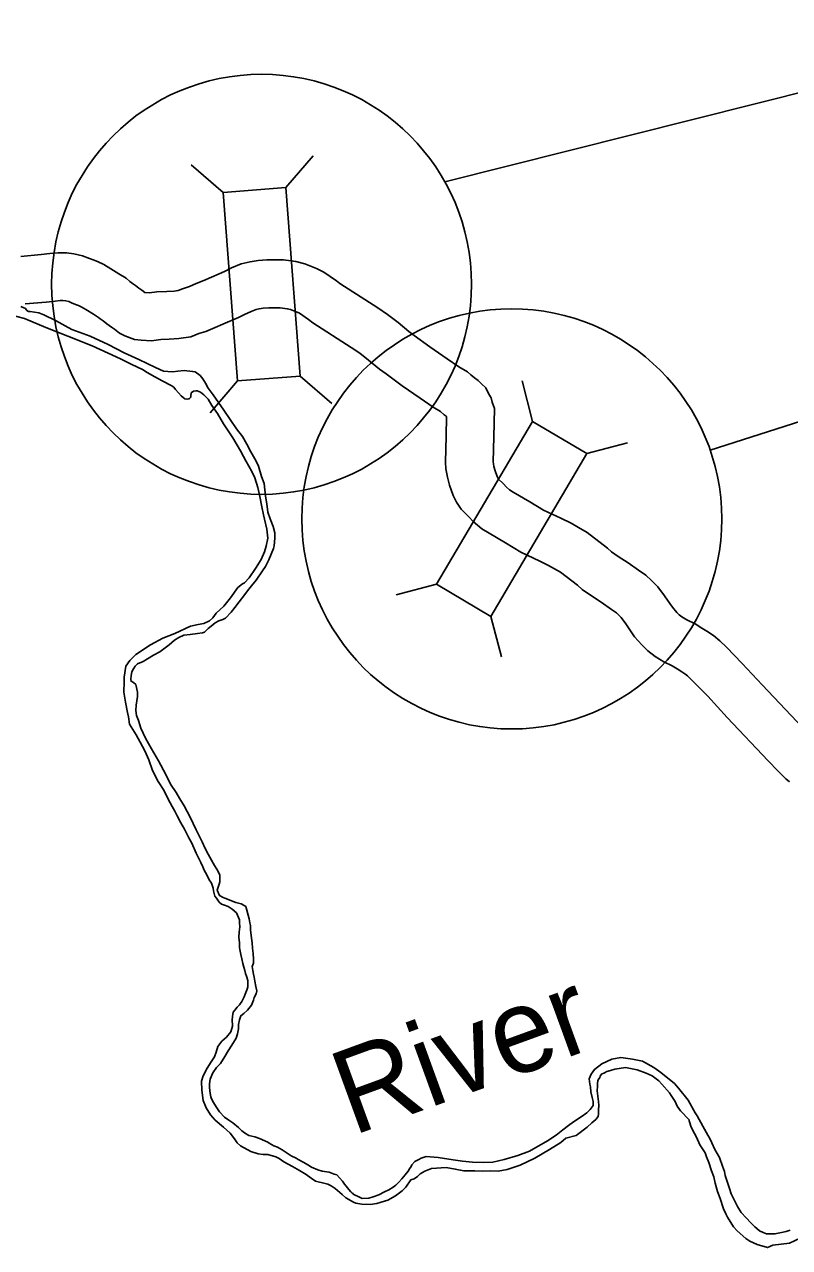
# Model space of a CAD drawing. Extents: x 79818 to 83933, y 50884 to 53307.
# Drawn here: x 81014.4 to 81078.5, y 53005.3 to 53107.7 of the extents above; entities that cross this region are included whole.
import ezdxf

# ---------------------------------------------------------------- set-up
doc = ezdxf.new("R2010")
doc.units = 0
for name, color, linetype in [('Default', 7, 'Continuous'), ('Level 10', 7, 'Continuous'), ('Level 20', 7, 'Continuous'), ('Level 9', 7, 'Continuous')]:
    doc.layers.add(name, color=color, linetype=linetype)

msp = doc.modelspace()

# ---------------------------------------------------------------- linework, layer by layer
at = {"layer": 'Default'}
for p in [(81049.64, 53094.55), (81071.88, 53072.06)]:
    msp.add_line(p, (81483.45, 53203.33), dxfattribs=at)
for centre in [(81034.28, 53085.95), (81055.25, 53066.3)]:
    msp.add_circle(centre, 17.6, dxfattribs=at)
at = {"layer": 'Level 10'}
for points in [[(81014.11, 53088.29), (81015.81, 53088.44), (81016.53, 53088.53), (81017.24, 53088.6), (81017.92, 53088.58), (81018.53, 53088.51), (81019.28, 53088.35), (81019.86, 53088.12), (81020.17, 53087.99), (81020.52, 53087.86), (81021.05, 53087.6), (81021.64, 53087.26), (81022.3, 53086.83), (81022.92, 53086.46), (81023.24, 53086.2), (81023.46, 53086.03), (81023.7, 53085.84), (81023.99, 53085.63), (81024.25, 53085.45), (81024.5, 53085.27), (81024.52, 53085.26), (81024.53, 53085.26), (81024.89, 53085.24), (81025.49, 53085.32), (81026.33, 53085.34), (81026.94, 53085.39), (81027.3, 53085.43), (81027.65, 53085.58), (81028.23, 53085.76), (81028.8, 53086.01), (81029.45, 53086.28), (81030.73, 53086.84), (81031.16, 53087.03), (81031.76, 53087.32), (81032.56, 53087.66), (81033.31, 53087.84), (81033.98, 53087.94), (81034.73, 53087.99), (81035.17, 53087.99), (81036.11, 53087.99), (81037.14, 53087.85), (81037.9, 53087.68), (81038.88, 53087.29), (81039.5, 53086.98), (81040.55, 53086.24), (81040.85, 53086.02), (81044.01, 53083.98), (81044.84, 53083.41), (81045.72, 53082.74), (81046.62, 53082), (81047.07, 53081.67), (81048.38, 53080.71), (81049.83, 53079.7), (81050.81, 53079.04), (81051.53, 53078.61), (81051.83, 53078.38), (81052.13, 53078.11), (81052.43, 53077.88), (81052.7, 53077.6), (81053.07, 53077.27), (81053.34, 53076.74), (81053.51, 53076.43), (81053.61, 53076.07), (81053.8, 53075.55), (81053.74, 53073.15)], [(81014.45, 53084.31), (81016.22, 53084.46), (81016.98, 53084.55), (81017.39, 53084.59), (81017.62, 53084.59), (81017.87, 53084.56), (81018.12, 53084.5), (81018.35, 53084.41), (81018.69, 53084.27), (81018.93, 53084.18), (81019.17, 53084.06), (81019.55, 53083.84), (81020.18, 53083.44), (81020.62, 53083.17), (81020.75, 53083.07), (81020.99, 53082.88), (81021.3, 53082.64), (81021.69, 53082.35), (81021.95, 53082.18), (81022.38, 53081.87), (81022.82, 53081.63), (81023.62, 53081.32), (81024.19, 53081.27), (81025.06, 53081.23), (81025.82, 53081.33), (81026.53, 53081.35), (81027.33, 53081.41), (81028.35, 53081.54), (81029.02, 53081.82), (81029.61, 53082), (81030.38, 53082.33), (81031.02, 53082.61), (81032.35, 53083.18), (81032.86, 53083.41), (81033.4, 53083.67), (81033.83, 53083.85), (81034.07, 53083.91), (81034.4, 53083.96), (81034.88, 53083.99), (81035.16, 53083.99), (81035.85, 53083.99), (81036.43, 53083.91), (81036.7, 53083.85), (81037.25, 53083.63), (81037.45, 53083.53), (81038.2, 53083), (81038.57, 53082.73), (81041.79, 53080.65), (81042.5, 53080.17), (81043.23, 53079.61), (81044.17, 53078.83), (81044.71, 53078.44), (81046.05, 53077.45), (81047.58, 53076.4), (81048.65, 53075.67), (81049.27, 53075.3), (81049.27, 53075.3), (81049.57, 53075.03), (81049.74, 53074.9), (81049.78, 53074.86), (81049.74, 53073.25)], [(81049.74, 53073.23), (81049.7, 53071.04), (81049.72, 53070.49), (81049.85, 53069.79), (81050.04, 53069.11), (81050.34, 53068.27), (81050.63, 53067.71), (81051, 53067.12), (81051.64, 53066.48), (81052.02, 53066.07), (81052.73, 53065.46), (81053.36, 53065.09), (81054.72, 53064.29), (81056.02, 53063.5), (81057.61, 53062.77), (81058.34, 53062.4), (81058.84, 53062.12), (81059.32, 53061.84), (81060.75, 53060.74), (81061.15, 53060.39), (81061.92, 53059.85), (81062.75, 53059.31), (81063.6, 53058.72), (81064.02, 53058.43), (81064.17, 53058.29), (81064.42, 53058.03), (81064.81, 53057.5), (81065.21, 53056.93), (81065.55, 53056.43), (81066.15, 53055.74), (81066.65, 53055.24), (81067.26, 53054.78), (81068, 53054.33), (81068.68, 53053.99), (81069.1, 53053.74), (81069.5, 53053.49), (81069.76, 53053.33), (81069.97, 53053.14), (81070.46, 53052.68), (81071.67, 53051.44), (81073.31, 53049.67), (81076.74, 53046.02), (81077.55, 53045.19), (81078.21, 53044.53), (81078.54, 53044.27)], [(81053.74, 53073.17), (81053.7, 53071.08), (81053.71, 53070.91), (81053.75, 53070.7), (81053.85, 53070.33), (81054.03, 53069.85), (81054.11, 53069.68), (81054.14, 53069.64), (81054.52, 53069.26), (81054.81, 53068.95), (81055.06, 53068.73), (81055.38, 53068.54), (81056.77, 53067.72), (81057.9, 53067.04), (81059.35, 53066.37), (81060.22, 53065.93), (81060.84, 53065.58), (81061.56, 53065.16), (81063.28, 53063.84), (81063.62, 53063.55), (81064.16, 53063.16), (81065, 53062.62), (81065.87, 53062), (81066.49, 53061.58), (81066.97, 53061.15), (81067.48, 53060.61), (81068.05, 53059.85), (81068.5, 53059.2), (81068.72, 53058.89), (81069.09, 53058.46), (81069.29, 53058.26), (81069.5, 53058.1), (81069.93, 53057.84), (81070.61, 53057.5), (81071.19, 53057.15), (81071.61, 53056.89), (81072.17, 53056.54), (81072.68, 53056.08), (81073.26, 53055.54), (81074.57, 53054.19), (81076.23, 53052.4), (81079.64, 53048.78)]]:
    msp.add_lwpolyline(points, dxfattribs=at)
at = {"layer": 'Level 20'}
for p, q in [((81036.32, 53094.05), (81038.61, 53096.72)), ((81031.05, 53093.65), (81028.38, 53095.95)), ((81037.51, 53078.26), (81040.18, 53075.96)), ((81032.25, 53077.86), (81029.96, 53075.19)), ((81057, 53074.46), (81056.12, 53077.87)), ((81061.55, 53071.78), (81064.96, 53072.66)), ((81048.95, 53060.82), (81045.55, 53059.94)), ((81053.5, 53058.13), (81054.38, 53054.73))]:
    msp.add_line(p, q, dxfattribs=at)
for points in [[(81037.51, 53078.26), (81036.32, 53094.05), (81031.05, 53093.65), (81032.25, 53077.86)], [(81053.5, 53058.13), (81061.55, 53071.78), (81057, 53074.46), (81048.95, 53060.82)]]:
    msp.add_lwpolyline(points, close=True, dxfattribs=at)
at = {"layer": 'Level 9'}
for points in [[(81012.48, 53083.59), (81014.42, 53083.09), (81016.2, 53082.32), (81018.04, 53081.6), (81020.09, 53080.79), (81021.43, 53080.18), (81022.45, 53079.7), (81023.4, 53079.23), (81024.3, 53078.81), (81024.69, 53078.56), (81025.33, 53078.2), (81026, 53077.83), (81026.69, 53077.47), (81026.91, 53077.34), (81027.06, 53077.15), (81027.32, 53076.87), (81027.54, 53076.6), (81027.7, 53076.46), (81027.85, 53076.36), (81028.03, 53076.32), (81028.18, 53076.35), (81028.25, 53076.39), (81028.35, 53076.5), (81028.35, 53076.62), (81028.39, 53076.85), (81028.58, 53076.99), (81028.76, 53077.02), (81028.89, 53077.03), (81029.16, 53076.91), (81029.44, 53076.68), (81029.79, 53076.34), (81030.11, 53075.8), (81030.57, 53075.12), (81031.1, 53074.27), (81031.87, 53073.1), (81032.5, 53072), (81032.77, 53071.52), (81032.95, 53071.16), (81033.47, 53070.28), (81033.71, 53069.74), (81033.96, 53068.93), (81034.12, 53068.17), (81034.29, 53067.32), (81034.43, 53066.64), (81034.52, 53066.27), (81034.73, 53065.45), (81034.79, 53064.67), (81034.66, 53064), (81034.51, 53063.53), (81034.25, 53062.89), (81033.77, 53062.13), (81033.23, 53061.35), (81032.86, 53060.95), (81032.68, 53060.87), (81032.28, 53060.55), (81031.67, 53059.69), (81031.11, 53058.99), (81030.47, 53058.4), (81030.19, 53058.02), (81029.92, 53057.76), (81029.45, 53057.53), (81028.95, 53057.45), (81028.31, 53057.32), (81027.02, 53056.7), (81026, 53056.3), (81024.96, 53055.76), (81023.74, 53054.94), (81023.23, 53054.44), (81022.91, 53053.96), (81022.77, 53053.04), (81022.77, 53052.68), (81022.74, 53051.79), (81022.86, 53050.95), (81023.04, 53050.08), (81023.11, 53049.72), (81023.21, 53049.09), (81023.77, 53048.2), (81024.11, 53047.58), (81024.49, 53046.88), (81024.82, 53046.12)], [(81014.1, 53084.1), (81014.48, 53083.93), (81014.61, 53083.77), (81014.75, 53083.67), (81014.89, 53083.67), (81015.6, 53083.56), (81016.03, 53083.4), (81017, 53082.91), (81018.38, 53082.17), (81019.9, 53081.61), (81021.41, 53080.9), (81022.76, 53080.21), (81023.98, 53079.64), (81025.39, 53078.97), (81026.05, 53078.67), (81026.43, 53078.64), (81026.85, 53078.63), (81027.27, 53078.67), (81027.78, 53078.72), (81028.5, 53078.66), (81028.7, 53078.62), (81029.13, 53078.32), (81029.36, 53078.02), (81029.59, 53077.67), (81029.81, 53077.25), (81030.23, 53076.68), (81031.11, 53075.42), (81032.18, 53073.83), (81032.68, 53073.19), (81033.05, 53072.56), (81033.37, 53071.91), (81033.82, 53071.13), (81034.01, 53070.72), (81034.28, 53069.84), (81034.49, 53069.27), (81034.62, 53068.2), (81034.73, 53067.56), (81034.81, 53066.86), (81035, 53066.29), (81035.24, 53065.66), (81035.4, 53065.13), (81035.38, 53064.67), (81035.33, 53064.05), (81035.28, 53063.82), (81034.9, 53062.88), (81034.6, 53062.32), (81034.36, 53061.95), (81033.83, 53061.17), (81033.44, 53060.7), (81033.11, 53060.27), (81032.87, 53059.97), (81032.39, 53059.35), (81032.05, 53058.87), (81031.72, 53058.49), (81031.25, 53057.97), (81031.02, 53057.88), (81030.69, 53057.76), (81030.39, 53057.58), (81030.04, 53057.31), (81029.8, 53057.11), (81029.5, 53056.81), (81029.32, 53056.76), (81028.92, 53056.7), (81028.28, 53056.6), (81027.76, 53056.55), (81027.34, 53056.36), (81026.99, 53056.15), (81026.54, 53055.76), (81025.74, 53055.15), (81025.23, 53054.87), (81024.73, 53054.57), (81024.35, 53054.36), (81023.88, 53054.16), (81023.69, 53053.95), (81023.53, 53053.73), (81023.39, 53053.48), (81023.34, 53053.19), (81023.31, 53052.84), (81023.34, 53052.7), (81023.54, 53052.58), (81023.75, 53052.41), (81023.87, 53051.77), (81023.87, 53051.42), (81023.77, 53050.7), (81023.75, 53050.24), (81023.79, 53049.84), (81023.96, 53049.41), (81024.16, 53048.77), (81024.55, 53047.94), (81025.04, 53047.02), (81025.64, 53046.04)], [(81024.82, 53046.12), (81025.13, 53045.22), (81025.61, 53044.31), (81026.08, 53043.56), (81026.44, 53042.81), (81026.78, 53042.2), (81027, 53041.81), (81027.21, 53041.41), (81027.52, 53040.83), (81027.82, 53040.29), (81028.18, 53039.59), (81028.43, 53039.13), (81028.8, 53038.29), (81029.2, 53037.51), (81029.36, 53037.15), (81029.46, 53036.87), (81029.58, 53036.66), (81029.93, 53035.98), (81030.06, 53035.84), (81030.12, 53035.69), (81030.21, 53035.37), (81030.24, 53035.13), (81030.35, 53034.69), (81030.49, 53034.52), (81030.72, 53034.19), (81030.93, 53034.03), (81031.17, 53033.95), (81031.47, 53033.82), (81031.8, 53033.61)], [(81025.64, 53046.04), (81026.25, 53044.87), (81026.65, 53044.07), (81027.11, 53043.37), (81027.44, 53042.84), (81027.78, 53042.27), (81028.3, 53041.31), (81028.8, 53040.25), (81029.29, 53039.23), (81029.55, 53038.69), (81029.79, 53038.22), (81030.22, 53037.45), (81030.33, 53037.25), (81030.6, 53036.82), (81030.77, 53036.46), (81030.79, 53035.9), (81030.71, 53035.7), (81030.56, 53035.2), (81030.75, 53034.74), (81031.07, 53034.59), (81031.19, 53034.53), (81032.12, 53034.15), (81032.56, 53034.05), (81032.83, 53033.92), (81032.96, 53033.83)], [(81031.8, 53033.61), (81032.19, 53033.29), (81032.43, 53032.71), (81032.44, 53032.47), (81032.45, 53032.13), (81032.4, 53031.67), (81032.36, 53031.26), (81032.42, 53030.79), (81032.43, 53030.39), (81032.46, 53030.23), (81032.55, 53029.79), (81032.61, 53029.45), (81032.72, 53029.04), (81032.8, 53028.75), (81032.88, 53028.47), (81032.94, 53028.2), (81033.01, 53027.99), (81033.12, 53027.62), (81033.13, 53027.52), (81033.13, 53027.1), (81033.08, 53026.89), (81032.91, 53026.48), (81032.82, 53026.25), (81032.62, 53025.86), (81032.44, 53025.59), (81032.23, 53025.39), (81032.03, 53025.15), (81031.91, 53024.96), (81031.83, 53024.62), (81031.81, 53024.3), (81031.83, 53023.89), (81031.83, 53023.81), (81031.69, 53023.32), (81031.34, 53022.89), (81030.96, 53022.53), (81030.62, 53022.09), (81030.48, 53021.63), (81030.32, 53021.23), (81030.05, 53020.81), (81029.71, 53020.28), (81029.39, 53019.64), (81029.24, 53019.19), (81029.27, 53018.44), (81029.39, 53017.58), (81029.64, 53016.97), (81030.01, 53016.38), (81030.4, 53015.92), (81031.09, 53015.34), (81031.64, 53014.84), (81032, 53014.37), (81032.23, 53014.02), (81032.52, 53013.77), (81033.38, 53013.3), (81033.99, 53013.09), (81034.41, 53013.04), (81034.79, 53013.05), (81035.47, 53012.84), (81035.74, 53012.72), (81036.15, 53012.44), (81036.86, 53012.03), (81037.45, 53011.71), (81038.01, 53011.38), (81038.44, 53011.07), (81038.8, 53010.82), (81039.6, 53010.62), (81039.83, 53010.55), (81040.11, 53010.43), (81040.44, 53010.21), (81040.83, 53009.86), (81041.02, 53009.7), (81041.35, 53009.41), (81041.98, 53009.04), (81042.18, 53008.96), (81042.69, 53008.89), (81043.37, 53008.87), (81043.93, 53008.93), (81044.29, 53009.05), (81044.85, 53009.23), (81045.5, 53009.58), (81046.06, 53010.01), (81046.36, 53010.31), (81046.8, 53010.93), (81047.06, 53011), (81047.35, 53011.2), (81047.57, 53011.43), (81047.97, 53011.65), (81048.52, 53011.88), (81049.76, 53011.95), (81050.51, 53011.83), (81051.23, 53011.69), (81052.14, 53011.69), (81052.76, 53011.66), (81053.46, 53011.67), (81054.1, 53011.64), (81054.87, 53011.79), (81055.96, 53012.15), (81057.17, 53012.73), (81058.4, 53013.48), (81059.35, 53014.06), (81059.77, 53014.41), (81060.65, 53014.63)], [(81032.96, 53033.83), (81033.23, 53032.78), (81033.29, 53032.46), (81033.35, 53032.22), (81033.36, 53031.86), (81033.39, 53031.61), (81033.46, 53030.97), (81033.49, 53030.78), (81033.51, 53030.32), (81033.58, 53029.9), (81033.59, 53029.42), (81033.61, 53029.07), (81033.5, 53028.79), (81033.54, 53028.47), (81033.6, 53028.16), (81033.65, 53027.91), (81033.71, 53027.56), (81033.81, 53027.12), (81033.88, 53026.77), (81033.82, 53026.5), (81033.66, 53026.21), (81033.59, 53025.97), (81033.44, 53025.55), (81033.1, 53025.13), (81032.78, 53024.87), (81032.54, 53024.67), (81032.42, 53024.34), (81032.34, 53023.94), (81032.34, 53023.58), (81032.26, 53023.15), (81032.16, 53022.8), (81031.78, 53022.21), (81031.48, 53021.73), (81031.19, 53021.26), (81030.83, 53020.66), (81030.51, 53020.33), (81030.2, 53019.88), (81029.98, 53019.36), (81029.92, 53018.97), (81029.91, 53018.73), (81029.94, 53018.36), (81030.02, 53017.89), (81030.09, 53017.71), (81030.25, 53017.39), (81030.46, 53017.03), (81030.74, 53016.61), (81031.17, 53016.17), (81031.52, 53015.91), (81031.88, 53015.69), (81032.33, 53015.32), (81032.63, 53015.04), (81032.85, 53014.85), (81033.2, 53014.64), (81033.71, 53014.52), (81034.11, 53014.39), (81034.8, 53014.07), (81034.91, 53014), (81035.3, 53013.78), (81035.62, 53013.67), (81035.99, 53013.43), (81036.43, 53013.15), (81036.77, 53012.94), (81037.18, 53012.74), (81037.35, 53012.63), (81037.82, 53012.37), (81038.16, 53012.18), (81038.45, 53011.99), (81039, 53011.75), (81039.37, 53011.65), (81039.94, 53011.58), (81040.35, 53011.41), (81040.59, 53011.33), (81041.05, 53010.81), (81041.24, 53010.57), (81041.37, 53010.4), (81041.58, 53010.12), (81041.75, 53009.92), (81041.87, 53009.81), (81041.95, 53009.77), (81041.96, 53009.72), (81042.54, 53009.44), (81042.72, 53009.37), (81043.27, 53009.39), (81043.62, 53009.49), (81044.11, 53009.67), (81044.59, 53009.92), (81044.95, 53010.1), (81045.3, 53010.31), (81045.52, 53010.47), (81045.79, 53010.73), (81046.03, 53011.02), (81046.31, 53011.34), (81046.56, 53011.65), (81046.69, 53011.84), (81046.81, 53012.03), (81046.87, 53012.19), (81047.11, 53012.47), (81047.45, 53012.64), (81047.66, 53012.74), (81048.08, 53012.87), (81049.09, 53012.79)], [(81049.09, 53012.79), (81050.35, 53012.61), (81051.11, 53012.5), (81051.95, 53012.41), (81052.92, 53012.37), (81053.67, 53012.41), (81054.6, 53012.64), (81055.77, 53012.97), (81056.73, 53013.33), (81058.23, 53014.2), (81058.98, 53014.67), (81059.53, 53015.11), (81060, 53015.47), (81060.42, 53015.77), (81061.07, 53016.19), (81061.54, 53016.53), (81061.83, 53016.81), (81062.07, 53017.15), (81062.06, 53017.48), (81061.99, 53017.83), (81061.88, 53018.3), (81061.84, 53018.71), (81061.8, 53018.94), (81061.75, 53019.38), (81061.91, 53019.77), (81062.17, 53020.18), (81062.79, 53020.64), (81063.65, 53021.03), (81064.38, 53021.16), (81065.37, 53021.03), (81066.21, 53020.86), (81067.16, 53020.34), (81067.74, 53019.93), (81068.88, 53018.99), (81069.22, 53018.61), (81070.03, 53017.59), (81070.62, 53016.54), (81070.78, 53016.3), (81071.25, 53015.43), (81071.67, 53014.67), (81071.82, 53014.45), (81072.03, 53014.02), (81072.28, 53013.48), (81072.65, 53012.8), (81072.91, 53012.06), (81073.08, 53011.62), (81073.14, 53011.28), (81073.35, 53010.62), (81073.49, 53010.19), (81073.65, 53009.75), (81073.88, 53009.25), (81074.02, 53008.96), (81074.16, 53008.69), (81074.48, 53008.19), (81074.9, 53007.73), (81075.29, 53007.33), (81075.63, 53007), (81075.78, 53006.85), (81076.02, 53006.64), (81076.33, 53006.51), (81076.61, 53006.41), (81077.3, 53006.39), (81077.85, 53006.51), (81078.24, 53006.61), (81078.57, 53006.71)], [(81060.65, 53014.63), (81061.56, 53015.33), (81061.96, 53015.71), (81062.29, 53015.99), (81062.49, 53016.24), (81062.53, 53016.43), (81062.53, 53016.8), (81062.54, 53017.15), (81062.51, 53017.5), (81062.46, 53017.94), (81062.44, 53018.17), (81062.42, 53018.39), (81062.43, 53018.77), (81062.44, 53019.02), (81062.47, 53019.23), (81062.49, 53019.3), (81062.64, 53019.5), (81062.67, 53019.62), (81062.77, 53019.77), (81063.03, 53019.89), (81063.23, 53020.01), (81063.52, 53020.08), (81063.88, 53020.2), (81064.77, 53020.33), (81065.76, 53020.14), (81066.52, 53019.86), (81067.03, 53019.64), (81067.58, 53019.21), (81067.82, 53018.94), (81068.46, 53018.21), (81068.62, 53017.99), (81068.95, 53017.48), (81069.12, 53017.1), (81069.38, 53016.7), (81070.11, 53015.94), (81070.13, 53015.87), (81070.28, 53015.35), (81070.56, 53014.82), (81070.72, 53014.5), (81071, 53013.86), (81071.45, 53013.18), (81071.58, 53012.86), (81071.77, 53012.39), (81072, 53011.69), (81072.18, 53011.19), (81072.29, 53010.64), (81072.49, 53009.96), (81072.72, 53009.37), (81073, 53008.5), (81073.18, 53008.08), (81073.32, 53007.81), (81073.83, 53006.98), (81074.14, 53006.64), (81074.86, 53006), (81075.21, 53005.8), (81075.81, 53005.5), (81076.69, 53005.25), (81077.13, 53005.45), (81078.53, 53005.63), (81079.49, 53006.07)]]:
    msp.add_lwpolyline(points, dxfattribs=at)

# ---------------------------------------------------------------- texts
msp.add_text('River', height=7.04, rotation=20, dxfattribs=at).set_placement((81041.91, 53014.6))

doc.saveas('drawing.dxf')
